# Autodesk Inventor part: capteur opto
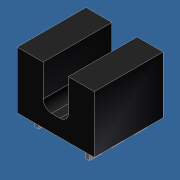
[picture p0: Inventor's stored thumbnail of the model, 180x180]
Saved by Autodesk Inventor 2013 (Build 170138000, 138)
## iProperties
Created: 2011-10
Part Number: capteur opto
Material: Nylon - 6/6
Document SubType Name: Modeling
Designer: Laur
Mass: 0.0578537 g
Surface Area: 1.09315 cm^2
Volume: 0.0511979 cm^3
Density: 1.13 g/cm^3
Author: Laur
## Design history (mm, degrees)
sketch "Esquisse1"
  geometry: L1 (13.326, 5.17)-(13.326, 0.52) reference; L2 (12.826, 0.02)-(10.776, 0.02) reference; L3 (10.276, 0.52)-(10.276, 5.17) reference; L4 (10.776, 5.67)-(12.826, 5.67) reference; L5 (-3.613, 12.119)-(-3.613, 7.319) reference; L6 (-4.113, 6.819)-(-16.713, 6.819) reference; L7 (-16.713, 6.819)-(-16.713, -8.877) reference; L8 (-16.272, -10.13)-(-14.837, -11.914) reference; L9 (-12.613, -11.131)-(-12.613, -4.381) reference; L10 (-12.113, -3.881)-(9.987, -3.881) reference; L11 (10.487, -4.381)-(10.487, -4.681) reference; L12 (10.987, -5.181)-(11.237, -5.181) reference; L13 (11.737, -5.681)-(11.737, -6.981) reference; L14 (11.237, -7.481)-(10.487, -7.481) reference; L15 (10.487, -7.481)-(10.487, -12.381) reference; L16 (10.487, -12.381)-(13.587, -12.381) reference; L17 (15.587, -10.381)-(15.587, 6.819) reference; L18 (15.587, 6.819)-(14.887, 6.819) reference; L19 (14.387, 7.319)-(14.387, 9.434) reference; L20 (14.267, 9.759)-(11.537, 12.944) reference; L21 (11.157, 13.119)-(-2.613, 13.119) reference; L22 (-2.613, 13.119)-(-3.613, 12.119) reference; L23 (-10.913, 0.819)-(-15.513, 0.819); L24 (-15.513, 0.819)-(-15.513, 4.919); L25 (-15.513, 4.919)-(-10.913, 4.919); L26 (-10.913, 4.919)-(-10.913, 0.819); L27 (-14.456, 4.919)-(-14.456, 0.819); L28 (-12.606, 4.919)-(-12.606, 0.819); C1 r 1.075 at (-9.144, 5.136) reference; C2 r 1.075 at (7.356, -2.064) reference; A1 r 0.5 centre (12.826, 0.52) between (12.826, 0.02) and (13.326, 0.52) reference; A2 r 0.5 centre (10.776, 0.52) between (10.276, 0.52) and (10.776, 0.02) reference; A3 r 0.5 centre (10.776, 5.17) between (10.776, 5.67) and (10.276, 5.17) reference; A4 r 0.5 centre (12.826, 5.17) between (13.326, 5.17) and (12.826, 5.67) reference; A5 r 0.5 centre (-4.113, 7.319) between (-4.113, 6.819) and (-3.613, 7.319) reference; A6 r 2 centre (-14.713, -8.877) between (-16.713, -8.877) and (-16.272, -10.13) reference; A7 r 1.25 centre (-13.863, -11.131) between (-14.837, -11.914) and (-12.613, -11.131) reference; A8 r 0.5 centre (-12.113, -4.381) between (-12.113, -3.881) and (-12.613, -4.381) reference; A9 r 0.5 centre (9.987, -4.381) between (10.487, -4.381) and (9.987, -3.881) reference; A10 r 0.5 centre (10.987, -4.681) between (10.487, -4.681) and (10.987, -5.181) reference; A11 r 0.5 centre (11.237, -5.681) between (11.737, -5.681) and (11.237, -5.181) reference; A12 r 0.5 centre (11.237, -6.981) between (11.237, -7.481) and (11.737, -6.981) reference; A13 r 2 centre (13.587, -10.381) between (13.587, -12.381) and (15.587, -10.381) reference; A14 r 0.5 centre (14.887, 7.319) between (14.387, 7.319) and (14.887, 6.819) reference; A15 r 0.5 centre (13.887, 9.434) between (14.387, 9.434) and (14.267, 9.759) reference; A16 r 0.5 centre (11.157, 12.619) between (11.537, 12.944) and (11.157, 13.119) reference
  constraints: 12 end point, 4 point on line, 3 perpendicular, 2 parallel, 1 horizontal
  dimensions: "d0" = 4.6 distance between parallel lines of L26 L24; "d1" = 4.1 distance between parallel lines of L25 L23; "d2" = 1.2 distance between parallel lines of L24 L7; "d3" = 1.9 distance between parallel lines of L6 L25
extrude "base" new body sketch "Esquisse1" distance "d4" = 1; taper "d5" = 0 deg
sketch "Esquisse2"
  geometry: L1 (-10.913, 0.819)-(-15.513, 0.819) reference; L2 (-10.913, 4.919)-(-10.913, 0.819) reference; L3 (-15.513, 4.919)-(-10.913, 4.919) reference; L4 (-15.513, 0.819)-(-15.513, 4.919) reference; L5 (-13.963, 4.919)-(-13.963, 0.819); L6 (-12.463, 4.919)-(-12.463, 0.819)
  constraints: 4 end point, 4 point on line, 2 perpendicular
  dimensions: "d6" = 1.5 distance between parallel lines of L6 L5; "d7" = 1.55 distance between parallel lines of L4 L5 (computed from d6)
extrude "fourche" join sketch "Esquisse2" distance "d8" = 2.4; taper "d9" = 0 deg
fillet "Congé1" dims "d10" = 0.5, "d11" = 0.5
sketch "Esquisse3"
  geometry: L1 (12.113, 3.334)-(11.891, 3.334); L2 (11.891, 3.334)-(11.891, 2.632); L3 (11.891, 2.632)-(12.113, 2.632); L4 (12.113, 2.632)-(12.113, 3.334); L5 (12.103, 4.711)-(11.88, 4.711); L6 (11.88, 4.711)-(11.88, 4.009); L7 (11.88, 4.009)-(12.103, 4.009); L8 (12.103, 4.009)-(12.103, 4.711); L9 (12.11, 2.013)-(11.887, 2.013); L10 (11.887, 2.013)-(11.887, 1.311); L11 (11.887, 1.311)-(12.11, 1.311); L12 (12.11, 1.311)-(12.11, 2.013); L13 (15.256, 2.122)-(15.034, 2.122); L14 (15.034, 2.122)-(15.034, 1.42); L15 (15.034, 1.42)-(15.256, 1.42); L16 (15.256, 1.42)-(15.256, 2.122); L17 (15.206, 4.543)-(14.983, 4.543); L18 (14.983, 4.543)-(14.983, 3.841); L19 (14.983, 3.841)-(15.206, 3.841); L20 (15.206, 3.841)-(15.206, 4.543)
  constraints: 40 end point, 10 parallel, 5 horizontal, 5 perpendicular
node "Plan de construction1"
extrude "5 pattes" join sketch "Esquisse3" distance "d12" = 1.5; taper "d13" = 0 deg
node "Solide1"
node "Corps solides"
node "Corps surfaciques"
node "Référence1"
